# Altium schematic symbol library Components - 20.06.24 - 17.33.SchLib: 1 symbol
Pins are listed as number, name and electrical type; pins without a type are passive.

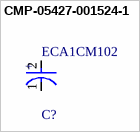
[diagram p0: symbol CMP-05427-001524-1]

## CMP-05427-001524-1
designator C?, comment ECA1CM102
Aluminum Electrolytic Capacitors (Radial Lead Type) 1000uF ±20% 16V; Life (Hours): 2000Hour; Ripple Current (AC): 680mA; Polarity: Polar; Lead/Base Style: Straight; Lead Diameter: 0.6mm; Capacitance: 1mF; Leakage Current: 3uA; Dissipation Factor: 0.2%
footprint FP-RAD-TH-D_10_0_5-L_16_1-MFG
pins: 1 C, 2 A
